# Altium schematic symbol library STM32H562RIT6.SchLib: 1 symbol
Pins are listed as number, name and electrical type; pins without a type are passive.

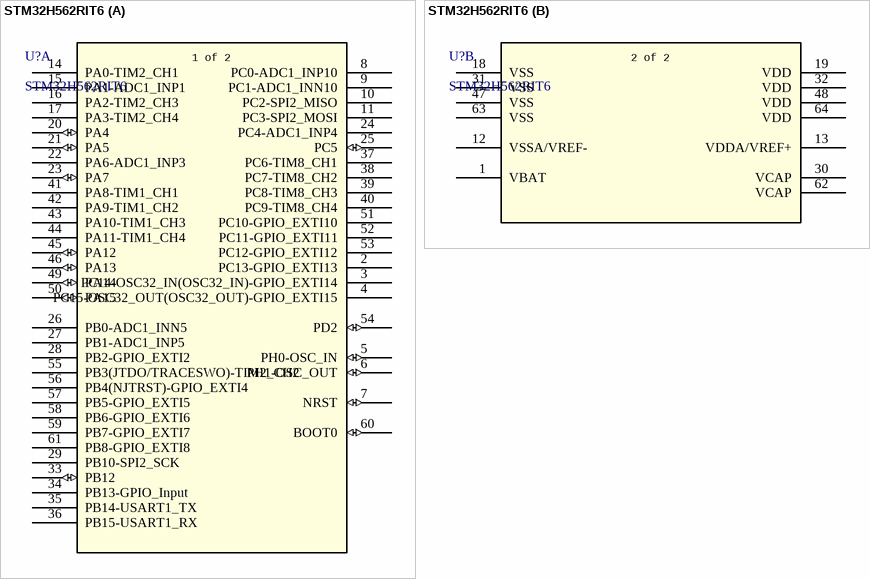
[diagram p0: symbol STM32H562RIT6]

## STM32H562RIT6
designator U?
High-performance, Arm Cortex-M33 with TrustZone, MCU with 2-Mbyte Flash, 640-Kbyte RAM, 250 MHz CPU; Manufacturer_Name: STMicroelectronics
footprint LQFP64-10x10mm_STM
part A pins: 2 PC13-GPIO_EXTI13, 3 PC14-OSC32_IN(OSC32_IN)-GPIO_EXTI14, 4 PC15-OSC32_OUT(OSC32_OUT)-GPIO_EXTI15, 5 PH0-OSC_IN (io), 6 PH1-OSC_OUT (io), 7 NRST (io), 8 PC0-ADC1_INP10, 9 PC1-ADC1_INN10, 10 PC2-SPI2_MISO, 11 PC3-SPI2_MOSI, 14 PA0-TIM2_CH1, 15 PA1-ADC1_INP1, 16 PA2-TIM2_CH3, 17 PA3-TIM2_CH4, 20 PA4 (io), 21 PA5 (io), 22 PA6-ADC1_INP3, 23 PA7 (io), 24 PC4-ADC1_INP4, 25 PC5 (io), 26 PB0-ADC1_INN5, 27 PB1-ADC1_INP5, 28 PB2-GPIO_EXTI2, 29 PB10-SPI2_SCK, 33 PB12 (io), 34 PB13-GPIO_Input, 35 PB14-USART1_TX, 36 PB15-USART1_RX, 37 PC6-TIM8_CH1, 38 PC7-TIM8_CH2, 39 PC8-TIM8_CH3, 40 PC9-TIM8_CH4, 41 PA8-TIM1_CH1, 42 PA9-TIM1_CH2, 43 PA10-TIM1_CH3, 44 PA11-TIM1_CH4, 45 PA12 (io), 46 PA13 (io), 49 PA14 (io), 50 PA15 (io), 51 PC10-GPIO_EXTI10, 52 PC11-GPIO_EXTI11, 53 PC12-GPIO_EXTI12, 54 PD2 (io), 55 PB3(JTDO/TRACESWO)-TIM2_CH2, 56 PB4(NJTRST)-GPIO_EXTI4, 57 PB5-GPIO_EXTI5, 58 PB6-GPIO_EXTI6, 59 PB7-GPIO_EXTI7, 60 BOOT0 (io), 61 PB8-GPIO_EXTI8
part B pins: 1 VBAT (power), 12 VSSA/VREF- (power), 13 VDDA/VREF+ (power), 18 VSS (power), 19 VDD (power), 30 VCAP (power), 31 VSS (power), 32 VDD (power), 47 VSS (power), 48 VDD (power), 62 VCAP (power), 63 VSS (power), 64 VDD (power)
